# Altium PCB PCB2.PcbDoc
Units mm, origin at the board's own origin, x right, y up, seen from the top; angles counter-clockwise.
Board outline 148.08 x 97.66 mm, 2 copper layers (Top Layer, Bottom Layer); 81 components, 33 nets, 200 pads, 0 vias.
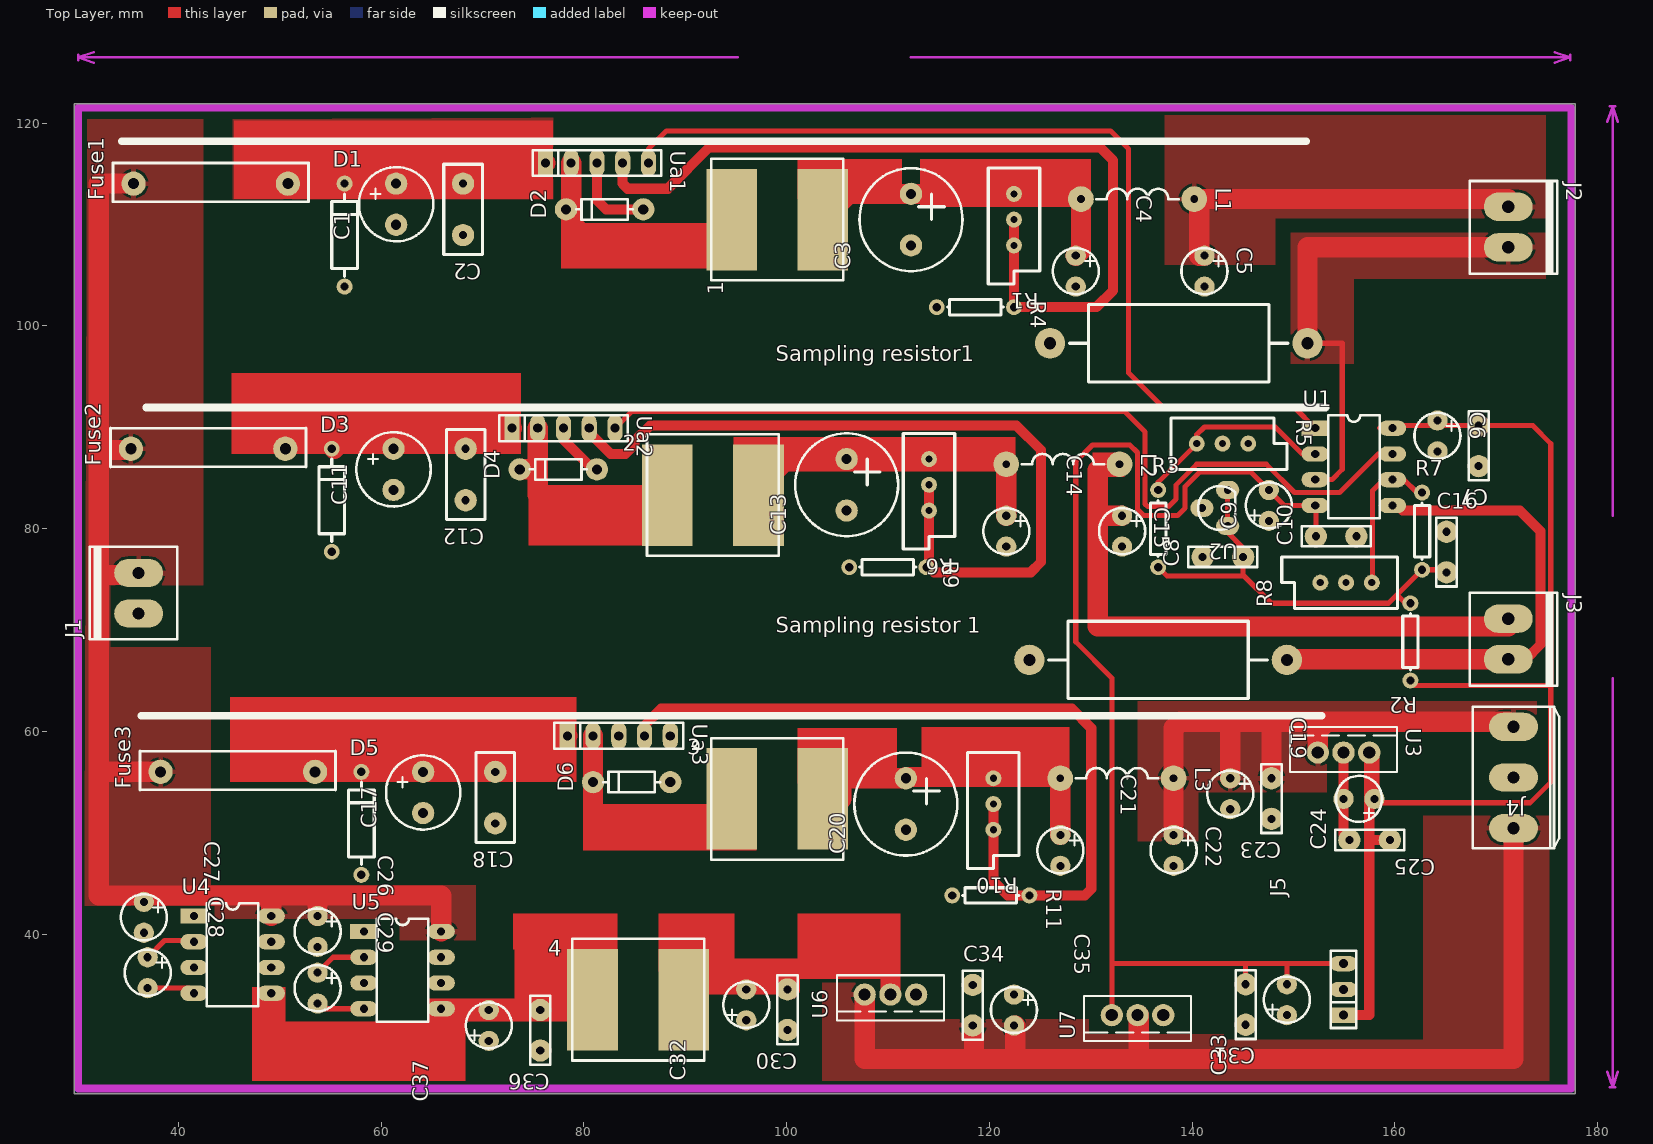
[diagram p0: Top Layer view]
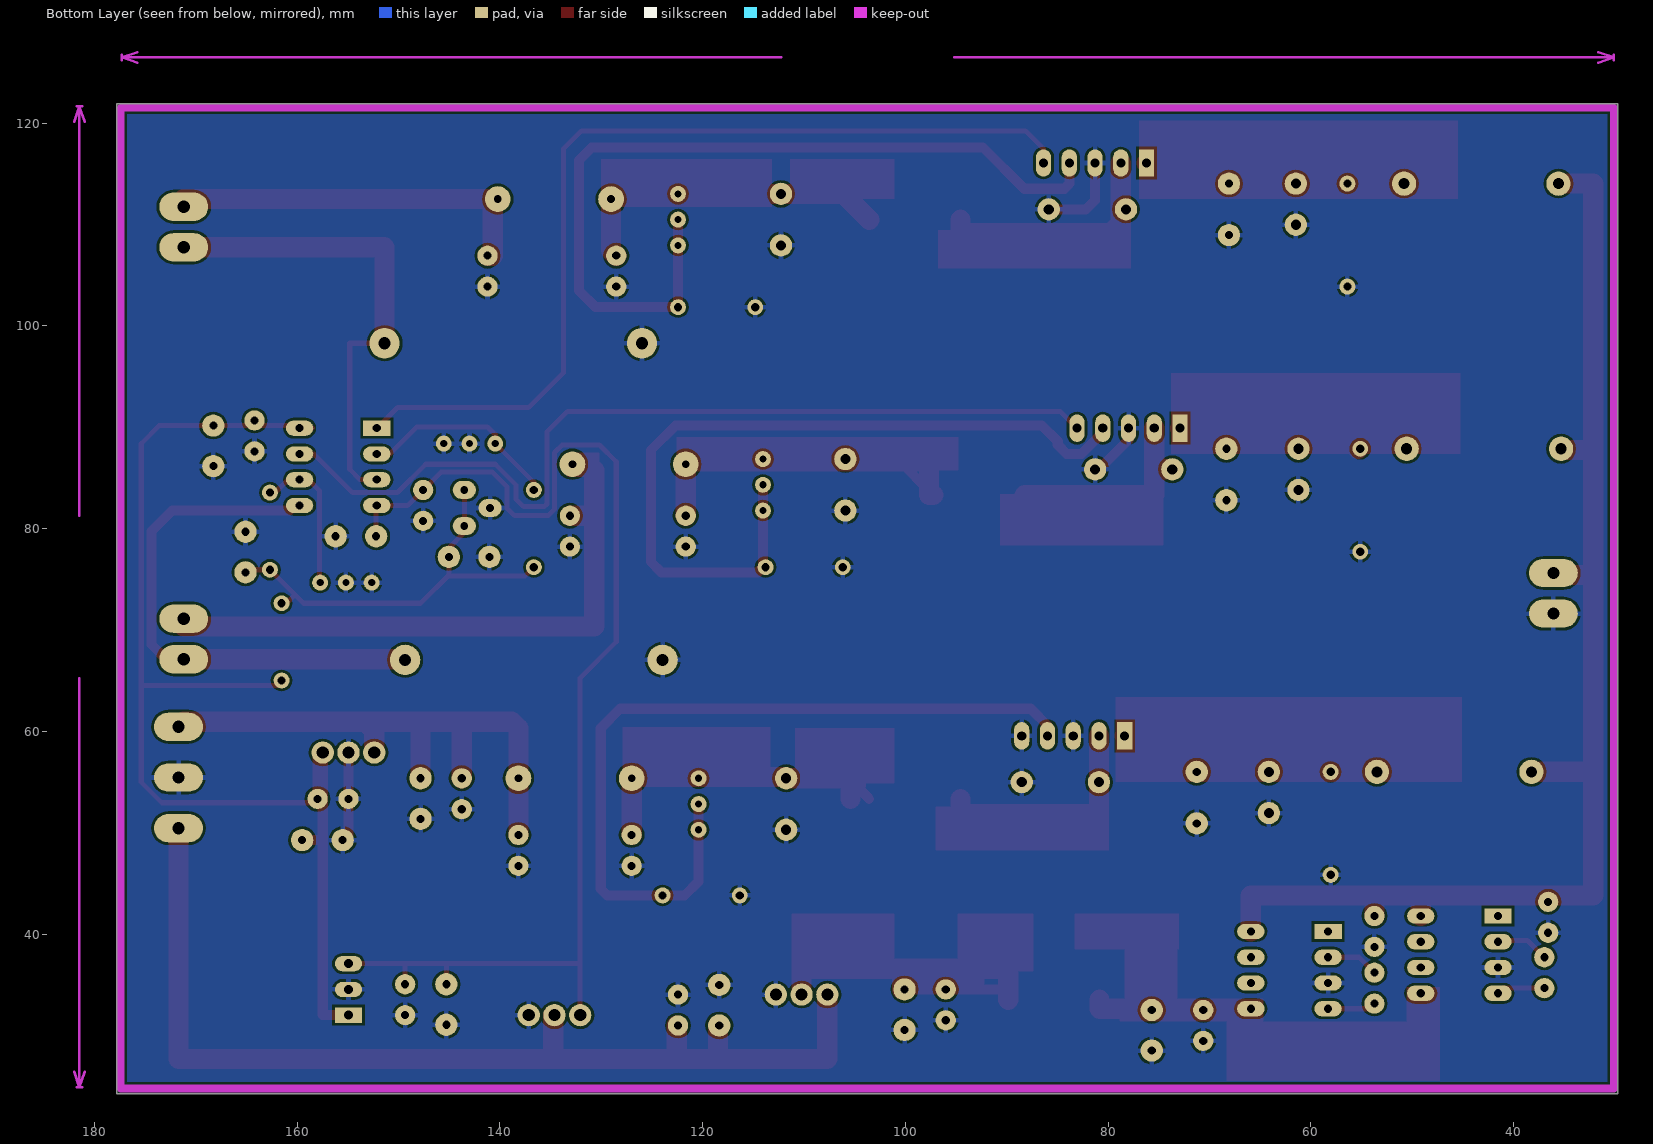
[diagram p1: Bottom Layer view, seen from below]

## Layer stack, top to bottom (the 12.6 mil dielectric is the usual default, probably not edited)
Top Layer: signal copper 0.0356
Dielectric: dielectric 0.32, FR-4, Dk 4.8
Bottom Layer: signal copper 0.0356

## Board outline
29.718,24.257 29.718,121.92 57.023,121.92 177.8,121.92 177.8,100.965 177.8,24.257 158.496,24.257

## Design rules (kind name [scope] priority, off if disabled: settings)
Clearance [All] p1: gap=0.254
PolygonConnect [All] p1: connectstyle=Relief reliefconductorwidth=0.5 reliefentries=4 polygonreliefangle="90 Angle"
RoutingVias [All] p1: holewidth=0.711 width=1.27 viastyle="Through Hole" minholewidth=0.711 minwidth=1.27 maxholewidth=0.711 maxwidth=1.27
SilkscreenOverComponentPads [All] p1 off: minsilkscreentomaskgap=0.254
SolderMaskExpansion [All] p1: expansion=0.102
TestPointUsage [All] p1: valid=0 allowmultiple=FALSE
Testpoint [All] p1: side=15 testpointundercomponent=TRUE minsize=1.016 maxsize=2.54 preferedsize=1.524 minholesize=0 maxholesize=1.016 preferedholesize=0.813 testpointgrid=0.025 style=1023 order=0-112345678
Width Width_1 [All] p1: maxlimit=2 minlimit=0.254 preferedwidth=0.254 toplayer_minwidth=0.5 toplayer_prefwidth=1 bottomlayer_minwidth=1 bottomlayer_maxwidth=1 bottomlayer_prefwidth=1 minimp=50.000000 maximp=50.000000 favimp=50.000000
Width [OnLayer('Top Layer')] p2: maxlimit=1.2 minlimit=0.254 preferedwidth=0.254 toplayer_minwidth=0.5 toplayer_prefwidth=1 bottomlayer_maxwidth=0.254 minimp=50.000000 maximp=50.000000 favimp=50.000000
23 further rules are at their usual default settings.

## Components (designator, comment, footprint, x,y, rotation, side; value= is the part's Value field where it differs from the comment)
1 "330uh" L 99.568,110.49 r90 top
2 "330uh" L 93.218,83.312 r90 top
3 "330uh" L 99.568,53.34 r90 top
4 "330uh" L 85.852,33.528 r90 top
C1 "1000uf" RB2 60.96,114.046 r90 top
C2 "104" RAD0.2 68.072,114.046 r270 top
C3 "2000uh" RB3 112.268,113.03 r90 top
C4 "100uf" RB1 128.524,105.41 r270 top
C5 "100uf" RB1 141.224,105.41 r270 top
C6 "10uf" RB1 164.211,89.154 r270 top
C7 "104" RAD0.15 168.275,90.17 r270 top
C8 "104" RAD0.15 145.034,77.216 r180 top
C9 "10uf" RB1 147.574,82.296 r90 top
C10 "104" RAD0.15 156.21,79.248 r180 top
C11 "1000uf" RB2 60.706,87.884 r90 top
C12 "104" RAD0.2 68.326,87.884 r270 top
C13 "2000uf" RB3 105.918,86.868 r90 top
C14 "100uf3" RB1 121.666,79.756 r270 top
C15 "100" RB1 133.096,79.756 r270 top
C16 "104" RAD0.15 165.1,75.692 r90 top
C17 "1000uf" RB2 63.627,56.007 r90 top
C18 "104" RAD0.2 71.247,56.007 r270 top
C19 "10uf" RB1 143.764,53.848 r270 top
C20 "2000uf" RB3 111.76,55.372 r90 top
C21 "100uf" RB1 127,48.26 r270 top
C22 "100uf" RB1 138.176,48.26 r270 top
C23 "104" RAD0.15 147.828,55.372 r270 top
C24 "104" RAD0.15 159.512,49.276 r180 top
C25 "10uf" RB1 156.464,53.34 r180 top
C26 "100uf" RB1 53.721,40.259 r270 top
C27 "100uf" RB1 36.576,41.656 r270 top
C28 "10uf" RB1 36.957,36.195 r270 top
C29 "10uf" RB1 53.721,34.671 r270 top
C30 "104" RAD0.15 100.076,34.544 r270 top
C31 "104" RAD0.15 145.288,35.052 r270 top
C32 "10uf" RB1 96.012,33.02 r90 top
C33 "10uf" RB1 149.352,33.528 r90 top
C34 "104" RAD0.15 118.364,30.988 r90 top
C35 "10uf" RB1 122.428,32.512 r270 top
C36 "104" RAD0.15 75.692,32.512 r270 top
C37 "10uf" RB1 70.612,30.988 r90 top
D1 "IN4007" DIODE0.4 56.388,103.886 r90 top
D2 "MBR360" DIODE0.2 82.804,111.506 r180 top
D3 "IN4007" DIODE0.4 55.118,77.724 r90 top
D4 "MBR360" DIODE0.2 78.232,85.852 r180 top
D5 "IN4007" DIODE0.4 58.039,45.847 r90 top
D6 "MBR360" DIODE0.2 85.471,54.991 r180 top
Fuse1 "4A" RAD0.5 43.18,114.046 r180 top
Fuse2 "4A" RAD0.5 42.926,87.884 r180 top
Fuse3 "4A" RAD0.5 45.847,56.007 r180 top
J1 "CON2" BCON2 36.068,71.628 r90 top
J2 "CON2" BCON2 171.196,111.76 r270 top
J3 "CON2" BCON2 171.196,71.12 r270 top
J4 "CON3" BCON3 171.704,60.452 r270 top
J5 "CON3" sip-3 154.94,32.004 r90 top
L1 "20uh" LHF440 129.032,112.522 r0 top
L2 "20uh" LHF440 121.666,86.36 r0 top
L3 "20uh" LHF440 127,55.372 r0 top
R1 "50K" VR5 122.428,113.03 r270 top
R2 "1k" AXIAL0.3 161.544,72.644 r270 top
R3 "1k" AXIAL0.3 136.652,76.2 r90 top
R4 "1.21K" AXIAL0.3 114.808,101.854 r0 top
R5 "5k" VR5 140.462,88.392 r0 top
R6 "50k" VR5 114.046,86.868 r270 top
R7 "1k" AXIAL0.3 162.687,75.946 r90 top
R8 "5k" VR5 157.734,74.676 r180 top
R9 "1.21K" AXIAL0.3 106.172,76.2 r0 top
R10 "50k" VR5 120.396,55.372 r270 top
R11 "1.21k" AXIAL0.3 116.332,43.815 r0 top
"Sampling resistor1" "0.1" AXIAL1.0 151.384,98.298 r180 top
"Sampling resistor 1" "0.1   100w" AXIAL1.0 149.352,67.056 r180 top
U1 "OPA2228" DIP-8 152.146,89.916 r0 top
U2 "TL431" TO92B 143.51,80.264 r180 top
U3 "7805" TO257V 152.4,57.912 r0 top
U4 "ICL7662" DIP-8 41.529,41.783 r0 top
U5 "ICL7662" DIP-8 58.293,40.259 r0 top
U6 "7915" TO257V 112.776,34.036 r180 top
U7 "7905" TO257V 137.16,32.004 r180 top
Ua1 "LM2596HVADJ" SIP-5 76.2,116.078 r0 top
Ua2 "LM2596HVADJ" SIP-5 72.898,89.916 r0 top
Ua3 "LM2596HVADJ" SIP-5 78.359,59.563 r0 top

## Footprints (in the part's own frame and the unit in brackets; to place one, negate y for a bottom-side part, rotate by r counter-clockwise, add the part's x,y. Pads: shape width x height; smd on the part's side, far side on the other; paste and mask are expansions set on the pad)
AXIAL0.3 [mil]
  round 62 hole 32: 1(0,0) 2(300,0)
  silkscreen extent 41,-30 259,30
AXIAL1.0 [mm]
  round 3 hole 1.2: 1(0,0) 2(25.4,0)
  silkscreen extent 1.91,-3.81 23.49,3.81
BCON2 [mil]
  oval 110x190 hole 47.24: 1(0,0) 2(157.48,0)
  silkscreen extent -100,-150 260,190
BCON3 [mil]
  oval 110x190 hole 47.24: 1(0,0) 2(196.85,0) 3(393.7,0)
  silkscreen extent -79,-157 472,177
DIODE0.2 [mm]
  round 2.2 hole 1: 1(-3.048,0) 2(4.572,0)
  silkscreen extent -2.03,-1.02 3.56,1.02
DIODE0.4 [mil]
  round 62 hole 32: 1(0,0) 2(400,0)
  silkscreen extent 40,-50 360,50
DIP-8 [mm]
  rect 2.7x1.5 hole 0.8: 1(0,0)
  oval 2.7x1.5 hole 0.8: 2(0,-2.54) 3(0,-5.08) 4(0,-7.62) 5(7.62,-7.62) 6(7.62,-5.08) 7(7.62,-2.54) 8(7.62,0)
  silkscreen extent 1.27,-8.89 6.35,1.27
L [mm]
  rect 10x5 smd: 1(0,5) 2(0,-4)
  silkscreen extent -6,-6 6,7
LHF440 [mil]
  round 100 hole 30: 1(0,0) 2(440,0)
  silkscreen extent 60,0 380,40
RAD0.2 [mm]
  round 2.2 hole 0.8: 1(0,0) 2(5.08,0)
  silkscreen extent -1.91,-1.91 6.98,1.91
RAD0.5 [mm]
  round 2.4 hole 1.1: 1(-7.62,0) 2(7.62,0)
  silkscreen extent -9.65,-2.03 9.65,1.78
RAD0.15 [mm]
  round 2.2 hole 0.8: 1(0,0) 2(4,0)
  silkscreen extent -1.4,-1 5.4,1
RB1 [mm]
  round 2 hole 0.8: 1(-1.524,0) 2(1.524,0)
  silkscreen extent -2.27,-2.27 2.27,2.27
RB2 [mm]
  round 2.2 hole 1: 1(0,-0.508) 2(-4.064,-0.508)
  silkscreen extent -5.69,-4.17 1.63,3.15
RB3 [mm]
  round 2.2 hole 1: 1(0,0) 2(-5.08,0)
  silkscreen extent -7.62,-5.08 2.54,5.08
sip-3 [mm]
  rect 1.5x2.7 hole 0.9: 1(0,0)
  oval 1.5x2.7 hole 0.9: 2(2.54,0) 3(5.08,0)
  silkscreen extent -1.27,-1.27 6.35,1.27
SIP-5 [mm]
  rect 1.5x2.7 hole 0.9: 1(0,0)
  oval 1.5x2.7 hole 0.9: 2(2.54,0) 3(5.08,0) 4(7.62,0) 5(10.16,0)
  silkscreen extent -1.27,-1.27 11.43,1.27
TO92B [mil]
  oval 90x70 hole 30: 1(0,0) 2(100,-70) 3(0,-140)
  silkscreen extent -30,-155 115,15
TO257V [mm]
  round 2.2 hole 1.2: 1(0,0) 2(2.54,0) 3(5.08,0)
  silkscreen extent -2.75,-1.91 7.83,2.54
VR5 [mil]
  round 62 hole 28: 1(0,0) 2(100,0) 3(200,0)
  silkscreen extent -100,-100 350,100

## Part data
1 2 3 4: library part INDUCTOR2
C1 C3 C4 C5 C6 C9 C11 C13 C14 C15 C17 C19 C20 C21 C22 C25 C26 C27 C28 C29 C32 C33 C35 C37: library part CAP3
C2 C7 C8 C10 C12 C16 C18 C23 C24 C30 C31 C34 C36: library part CAP1
D1 D2 D3 D4 D5 D6: library part DIODE
Fuse1 Fuse2 Fuse3: library part FUSE1, "Fuse"
J1 J2 J3 J4 J5: "Connector"
L1 L2 L3: library part INDUCTOR
R1 R5 R6 R8 R10: library part RPOT2, "Potentiometer"
R2 R3 R4 R7 R9 R11 "Sampling resistor1" "Sampling resistor 1": library part RES
U1: library part NE5532
U2: "Programmable Voltage Reference"
U3: library part 78**
U6 U7: library part 79**
Ua1 Ua2 Ua3: library part LM2596T-5.0, "Simple Switcher Power Converter 150 kHz 3A Step Down Voltage Regulator"

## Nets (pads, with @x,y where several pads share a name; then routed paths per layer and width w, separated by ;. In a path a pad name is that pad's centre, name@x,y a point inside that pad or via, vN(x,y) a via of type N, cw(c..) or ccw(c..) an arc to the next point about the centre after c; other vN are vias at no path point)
"5V 3A": C5.1 J2.1 L1.2 | length 72.9
  Top Layer w1: L1.2 J2.1@170.434,112.522 ; L1.2@140.716,112.014 140.716,107.442 C5.1
  Top Layer w2: C5.1 140.716,106.934 140.716,112.522 171.196,112.522 J2.1
"8V 3A": C15.1 J3.1 L2.2 | length 59.1
  Top Layer w2: 130.683,85.768 130.683,81.28 ; C15.1 130.683,81.28 ; J3.1 171.196,70.358 130.683,70.358 130.683,81.28
+5V: C6.1 C7.1 C24.1 C25.1 J5.1 R2.2 U1.8 U3.3 | length 118
  Top Layer w0.5: C25.1 158.369,52.959 173.355,52.959 175.387,54.991 175.387,88.392 173.609,90.17 C7.1 U1.8@160.02,90.17 ; U1.8@158.496,89.916 U1.8 ; R2.2@161.544,64.516 175.133,64.516
  Top Layer w1: J5.1 157.48,32.004 157.48,49.276 ; C25.1 157.988,57.404 U3.3 157.48,49.276 ; C24.1 157.48,49.276
+15V: C19.1 C22.1 C23.1 J4.1 L3.2 U3.1 | length 58.2
  Top Layer w2: C22.1 L3.2 138.176,60.325 138.811,60.96 153.289,60.96 ; C19.1 143.764,60.198 ; C23.1 147.828,60.833 ; U3.1 152.4,60.071 153.289,60.96 ; J4.1 171.196,60.96 153.289,60.96
-5V: C9.2 C10.2 C31.1 C33.2 J5.3 U1.4 U7.3 | length 122
  Top Layer w0.5: U7.3@132.08,33.02 U7.3 132.08,37.084 ; C31.1 145.288,37.084 ; C33.2 149.352,37.084 ; C10.2 152.21,82.232 U1.4 149.098,82.296 C9.2 145.796,85.598 140.766,85.598 139.319,84.151 139.319,82.042 138.557,81.28 135.255,81.28 134.607,81.928 134.607,84.667 134.616,84.677 134.616,87.507 133.858,88.265 130.175,88.265 128.524,86.614 128.524,68.834 132.08,65.278 132.08,37.084 ; J5.3 149.352,37.084 ; 132.08,37.084 145.288,37.084 ; 145.288,37.084 149.352,37.084
-15V: C34.1 C35.2 J4.3 U6.3 U7.2 | length 111
  Top Layer w1: 118.364,29.083 C34.1 ; 122.428,29.083 C35.2 ; U7.2 134.747,31.877 134.874,31.75 134.874,28.956
  Top Layer w2: U6.3 107.696,27.686 118.491,27.686 ; C34.1@118.491,30.988 118.491,27.686 ; C35.2@122.555,30.988 122.555,27.686 ; U7.2@134.747,32.004 134.747,31.877 134.747,27.686 ; J4.3 171.704,27.686 134.747,27.686 ; 118.491,27.686 122.555,27.686 ; 122.555,27.686 134.747,27.686
FB5V: U1.1 Ua1.5 | length 93
  Top Layer w0.5: Ua1.5 86.36,117.475 88.138,119.253 131.953,119.253 133.731,117.475 133.731,95.377 137.16,91.948 150.114,91.948 U1.1
FB8V: U1.7 Ua2.5 | length 90.7
  Top Layer w0.5: Ua2.5 84.709,91.567 133.35,91.567 135.37,89.547 135.37,84.364 135.361,84.355 135.361,82.444 135.636,82.169 137.668,82.169 138.43,82.931 138.43,84.328 140.462,86.36 147.32,86.36 150.114,83.566 154.559,83.566 158.369,87.376 U1.7
GND: "Sampling resistor1.2" "Sampling resistor 1.2" C1.2 C2.2 C3.2 C4.2 C5.2 C6.2 C7.2 C8.2 C9.1 C10.1 C11.2 C12.2 C13.2 C14.2 C15.2 C16.2 C17.2 C18.2 C19.2 C20.2 C21.2 C22.2 C23.2 C24.2 C25.2 C26.2 C27.2 C30.2 C31.2 C32.1 C33.1 C34.2 C35.1 C36.2 C37.1 D1.1 D2.1 D3.1 D4.1 D5.1 D6.1 J1.1 J4.2 J5.2 R4.1 R5.2 R5.3 R8.2 R8.3 R9.1 R11.1 U2.2 U3.2 U4.3 U5.3 U6.1 U7.1 Ua1.3 Ua2.3 Ua3.3 Ua3.5 | length 23.4
  Top Layer w1: Ua2.3 77.978,88.773 80.899,85.852 D4.1@81.534,85.852 ; Ua1.3 81.28,112.395 82.169,111.506 D2.1 ; U3.2 C25.2 154.94,49.848 C24.2
Net1_1: 1.1 D2.2 Ua1.2 | length 40.8
  Top Layer w1: D2.2@78.74,110.871 79.959,109.652 93.73,109.652 1.1
  Top Layer w2: Ua1.2 78.74,109.152 94.568,109.152 1.1
Net1_2: 1.2 C3.1 C4.1 L1.1 R1.1 | length 32.5
  Top Layer w2: 1.2 106.108,113.03 C3.1 R1.1 128.524,113.03 L1.1 129.032,107.442 C4.1
Net2_1: 2.1 D4.2 Ua2.2 | length 21.2
  Top Layer w2: D4.2 75.438,85.852 ; Ua2.2 75.438,85.852 ; 2.1 75.438,83.312 75.438,85.852
Net2_2: 2.2 C13.1 C14.1 L2.1 R6.1 | length 58.6
  Top Layer w1: 2.2 100.774,86.868 C13.1 R6.1 L2.1@121.158,86.868
  Top Layer w2: 2.2 97.663,83.312 97.663,86.646 114.046,86.646 121.666,86.646 L2.1 C14.1
Net3_1: 3.1 D6.2 Ua3.2 | length 22.9
  Top Layer w2: Ua3.2 D6.2 80.899,51.816 94.568,51.816 3.1
Net3_2: 3.2 C20.1 C21.1 L3.1 R10.1 | length 33.7
  Top Layer w1: 3.2 104.902,54.674 104.902,54.991 105.41,55.499 3.2@105.727,55.499
  Top Layer w2: 3.2@104.902,54.674 3.2@105.727,55.499 ; 3.2@105.41,53.34 105.41,55.372 C20.1 ; C20.1@111.76,55.499 127,55.499 L3.1 C21.1
Net4_1: 4.1 C36.1 C37.2 U4.5 U5.5 | length 44.2
  Top Layer w1: 49.149,32.512 49.149,33.401 U4.5 ; C36.1@75.692,32.639 4.1@79.963,32.639
  Top Layer w2: 49.149,32.512 49.149,29.718 65.913,29.718 U5.5 75.692,32.639 80.852,32.639 4.1
Net4_2: 4.2 C30.1 C32.2 U6.2 | length 37.5
  Top Layer w1: 4.2@90.868,34.544 C32.2 C30.1 C30.1@100.33,34.544
  Top Layer w2: 4.2 89.852,36.576 95.631,36.576 100.33,36.576 ; C30.1@100.33,34.544 100.33,36.576 ; U6.2 110.236,36.576 100.33,36.576
NetC1_1: C1.1 C2.1 D1.2 Fuse1.1 Ua1.1 | length 33.5
  Top Layer w2: Fuse1.1 50.8,116.078 56.515,116.078 ; D1.2@56.515,114.046 56.515,116.078 ; C1.1@61.722,114.046 61.722,116.078 ; C2.1@67.945,114.046 67.945,116.078 ; Ua1.1 67.945,116.078 ; 56.515,116.078 61.722,116.078 ; 61.722,116.078 67.945,116.078
NetC8_1: C8.1 C16.1 R2.1 R3.1 R7.1 U2.1 U2.3 | length 42
  Top Layer w0.5: R3.1 137.541,75.311 144.907,75.311 145.034,75.438 ; U2.3 U2.1 143.51,79.629 145.034,78.105 145.034,75.438 ; R2.1@161.544,72.136 160.21,73.469 ; C16.1@164.846,75.946 R7.1 160.21,73.469 ; 145.034,75.438 147.828,72.644 159.385,72.644 160.21,73.469
NetC11_1: C11.1 C12.1 D3.2 Fuse2.1 Ua2.1 | length 30.5
  Top Layer w2: Fuse2.1 50.546,89.916 55.372,89.916 ; D3.2@55.372,87.884 55.372,89.916 ; C11.1@61.087,87.884 61.087,89.916 ; C12.1 68.326,89.916 ; Ua2.1 68.326,89.916 ; 55.372,89.916 61.087,89.916 ; 61.087,89.916 68.326,89.916
NetC17_1: C17.1 C18.1 D5.2 Fuse3.1 Ua3.1 | length 39.1
  Top Layer w2: Fuse3.1 54.102,56.007 54.102,59.563 58.039,59.563 ; D5.2 58.039,59.563 ; C17.1 64.135,59.563 ; C18.1 71.247,59.563 ; Ua3.1 71.247,59.563 ; 58.039,59.563 64.135,59.563 ; 64.135,59.563 71.247,59.563
NetC26_1: C26.1 C27.1 Fuse1.2 Fuse2.2 Fuse3.2 J1.2 U4.8 U5.8 | length 127.8
  Top Layer w2: J1.2@35.306,75.628 35.306,75.438 32.131,75.438 ; Fuse2.2 35.306,87.757 32.131,87.757 ; Fuse1.2 32.131,114.046 32.131,87.757 ; Fuse3.2 32.131,56.007 ; U4.8 49.149,43.806 ; C26.1 53.721,43.806 ; U5.8 65.913,43.806 53.721,43.806 ; 32.131,56.007 32.131,43.806 49.149,43.806 ; 32.131,56.007 32.131,75.438 ; 32.131,75.438 32.131,87.757 ; 49.149,43.806 53.721,43.806
NetC28_1: C28.1 U4.2 | length 5.3
  Top Layer w0.5: C28.1 38.608,39.37 41.402,39.37 U4.2
NetC28_2: C28.2 U4.4 | length 4.1
  Top Layer w0.5: C28.2 U4.4@41.021,34.671
NetC29_1: C29.1 U5.2 | length 5.2
  Top Layer w0.5: C29.1 55.245,37.719 U5.2
NetC29_2: C29.2 U5.4 | length 4.1
  Top Layer w0.5: C29.2@54.229,32.639 U5.4
NetJ2_2: "Sampling resistor1.1" J2.2 U1.3 | length 48.2
  Top Layer w0.5: 151.384,98.298 154.813,98.298 154.813,85.852 153.797,84.836 U1.3
  Top Layer w2: 151.384,98.298 151.384,107.76 J2.2
NetJ3_2: "Sampling resistor 1.1" J3.2 U1.5 | length 52.6
  Top Layer w1: U1.5 160.274,82.296 160.782,81.788 172.339,81.788 174.371,79.756 174.371,68.58 172.911,67.12 J3.2 J3.2@171.133,67.183
  Top Layer w2: 149.352,67.056 149.352,67.12 J3.2
NetR1_2: R1.2 R1.3 R4.2 Ua1.4 | length 84.8
  Top Layer w1: Ua1.4 83.82,114.046 84.328,113.538 88.265,113.538 92.329,117.602 130.937,117.602 132.207,116.332 132.207,103.505 130.556,101.854 R4.2 R1.3 R1.2
NetR3_2: R3.2 R5.1 U1.2 | length 20.1
  Top Layer w0.5: R3.2 136.652,84.582 R5.1 140.462,89.281 141.224,90.043 148.209,90.043 150.876,87.376 U1.2
NetR6_2: R6.2 R6.3 R9.2 Ua2.4 | length 79.1
  Top Layer w1: Ua2.4 80.518,89.49 82.632,87.376 84.074,87.376 84.964,88.266 84.964,88.624 86.51,90.17 122.682,90.17 125.095,87.757 125.095,76.708 124.079,75.692 114.554,75.692 114.046,76.2 R6.3 R6.2
NetR7_2: R7.2 R8.1 U1.6 | length 15
  Top Layer w0.5: R8.1 157.814,74.756 157.814,83.773 158.877,84.836 160.909,84.836 162.179,83.566 R7.2
NetR10_2: R10.2 R10.3 R11.2 Ua3.4 | length 80.5
  Top Layer w1: Ua3.4 85.979,60.579 87.63,62.23 128.143,62.23 130.048,60.325 130.048,44.45 129.413,43.815 R11.2 121.793,43.815 120.396,45.212 R10.3 R10.2
pads on no net: U4.1 U4.6 U4.7 U5.1 U5.6 U5.7

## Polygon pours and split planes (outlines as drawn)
NetC1_1 on Top Layer "Bottom Layer-No Net" (solid): 45.339,120.396 45.339,112.522 65.151,112.522 76.962,112.522 76.962,116.967 76.962,120.523 74.803,120.523
NetC26_1 on Top Layer "Bottom Layer-No Net" (solid): 30.988,120.396 42.418,120.396 42.418,116.713 42.418,74.422 38.481,74.422 33.274,74.422 33.274,74.676 33.274,68.326 42.291,68.326 43.18,68.326 43.18,44.831 58.928,44.831 69.342,44.831 69.342,40.64 69.342,39.37 67.437,39.37 61.849,39.37 61.849,41.529 52.705,41.529 43.561,41.529 43.561,42.799 35.179,42.799 30.734,42.799 30.734,45.339
+15V on Top Layer "Bottom Layer-No Net" (solid): 134.62,62.992 134.62,49.149 140.081,49.149 140.589,49.149 140.589,54.737 140.589,53.975 153.289,53.975 153.289,59.817 153.289,59.944 156.464,59.944 173.99,59.944 173.99,61.087 173.99,62.992 171.958,62.992
NetJ2_2 on Top Layer "Bottom Layer-No Net" (solid): 174.879,109.22 149.733,109.22 149.733,108.585 149.733,96.266 153.162,96.266 155.956,96.266 155.956,99.695 155.956,104.648 162.687,104.648 174.879,104.648 174.879,104.267
"5V 3A" on Top Layer "Bottom Layer-No Net" (solid): 139.319,120.777 174.879,120.777 174.879,112.268 174.879,110.617 170.307,110.617 148.209,110.617 148.209,110.236 148.209,106.045 143.637,106.045 137.287,106.045 137.287,106.426 137.287,120.777 139.573,120.777
-15V on Top Layer "Bottom Layer-No Net" (solid): 162.814,51.689 174.498,51.689 175.26,51.689 175.26,46.355 175.26,25.527 173.609,25.527 103.505,25.527 103.505,28.194 103.505,35.179 104.521,35.179 108.712,35.179 108.712,33.655 108.712,31.623 129.794,31.623 129.794,30.48 129.794,30.099 133.858,30.099 143.129,30.099 143.129,29.337 143.129,29.591 154.305,29.591 162.814,29.591 162.814,51.689
GND on Bottom Layer "Bottom Layer-No Net" (solid, pour order 1000): 30.099,117.475 30.099,121.539 41.148,121.539 177.419,121.539 177.419,107.569 177.419,24.765 162.56,24.765 30.099,24.765 30.099,28.575

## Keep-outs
Keep-Out Layer:
  lines w0.254: 30.099,126.238 30.099,126.746 ; 31.623,125.984 30.099,126.492 ; 31.623,127 30.099,126.492 ; 95.164,126.492 30.099,126.492 ; 112.227,126.492 177.292,126.492 ; 175.768,125.984 177.292,126.492 ; 175.768,127 177.292,126.492 ; 177.292,126.238 177.292,126.746 ; 180.975,26.416 181.483,24.892 ; 180.975,120.142 181.483,121.666 ; 181.229,24.892 181.737,24.892 ; 181.229,121.666 181.737,121.666 ; 181.483,65.255 181.483,24.892 ; 181.483,81.303 181.483,121.666 ; 181.991,26.416 181.483,24.892 ; 181.991,120.142 181.483,121.666
  lines w0.762: 30.988,121.539 177.419,121.539 177.419,24.765 30.099,24.765 30.099,121.539 36.068,121.539
  text "147.193 (mm)" at 95.418,125.578 h1.52
  text "96.774 (mm)" at 182.397,65.509 h1.52 r90

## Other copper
Top Layer:
  rectangle net NetC17_1: 45.085,54.991 79.248,63.373
  rectangle net NetC11_1: 45.212,87.376 73.787,95.377
  rectangle net NetC1_1: 45.466,112.522 76.962,120.269
  rectangle net Net4_1: 47.244,25.527 68.326,28.575
  rectangle net Net4_2: 92.202,34.036 100.584,37.592
  rectangle net "8V 3A": 130.175,85.09 133.35,87.503
  rectangle net Net3_1: 79.883,48.26 97.028,52.578
  rectangle net Net2_2: 94.742,85.725 122.555,89.027
  rectangle net Net2_1: 74.549,78.359 90.678,83.439
  rectangle net Net4_2: 105.41,36.703 111.252,42.037
  rectangle net Net4_1: 73.152,33.655 78.359,38.481
  rectangle net Net4_1: 64.643,31.369 78.867,33.655
  rectangle net Net4_1: 47.244,27.686 50.546,34.798
  rectangle net Net4_1: 50.165,27.686 68.326,31.369
  rectangle net Net4_2: 101.092,37.338 105.41,42.037
  rectangle net Net4_2: 87.376,36.322 94.869,42.037
  rectangle net Net3_2: 113.284,54.864 127.889,60.452
  rectangle net Net3_2: 101.092,54.864 110.871,60.325
  rectangle net Net1_2: 101.092,112.522 111.379,116.459
  rectangle net Net1_2: 113.157,111.76 130.048,116.459
  rectangle net Net1_1: 77.724,105.664 96.774,109.474
  rectangle net Net4_1: 73.025,38.481 83.312,42.037

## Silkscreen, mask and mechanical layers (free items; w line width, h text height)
Top Overlay:
  lines w0.762: 34.417,118.237 151.257,118.237 ; 36.335,61.531 152.794,61.531 ; 36.83,91.948 153.162,91.948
